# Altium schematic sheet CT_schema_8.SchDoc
size 308 x 210 mm
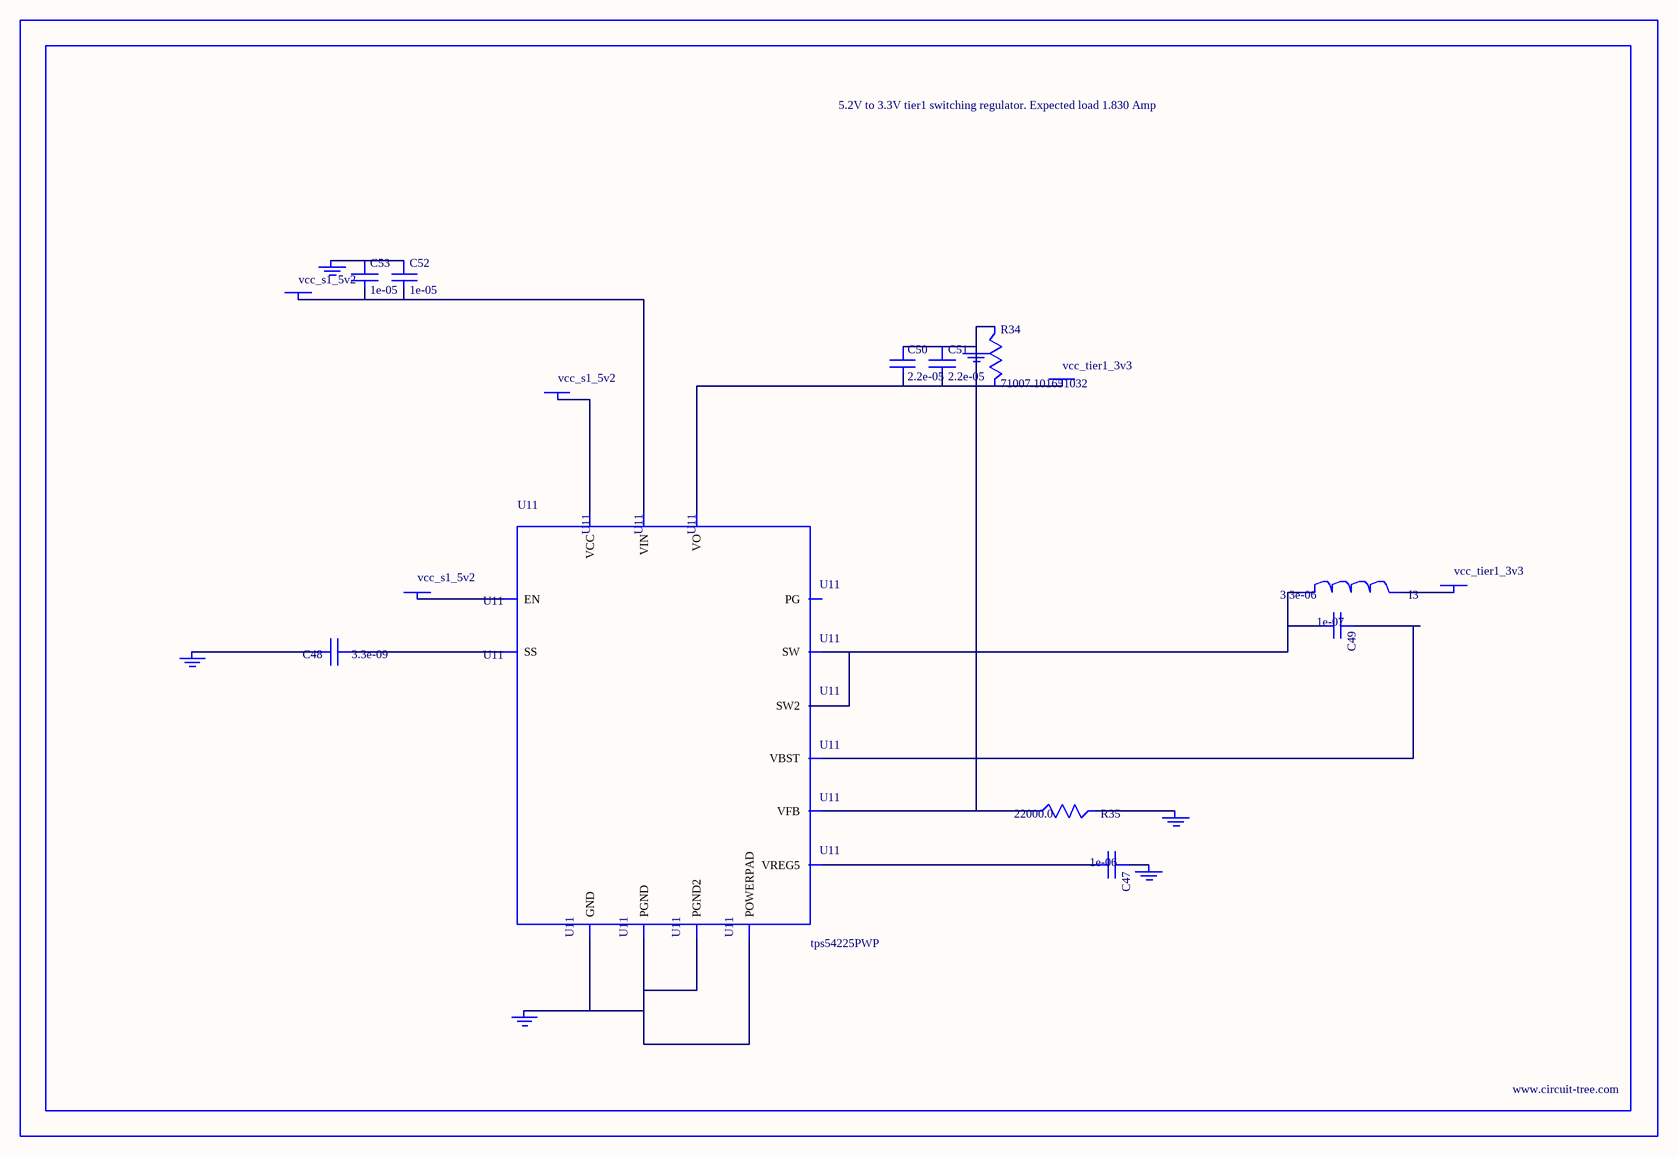
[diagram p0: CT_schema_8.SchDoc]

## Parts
BORDER7  (no value)
C47  1e-06  [C0603]
C48  3.3e-09  [C0402]
C49  1e-07  [C0402]
C50  2.2e-05  [C1210]
C51  2.2e-05  [C1210]
C52  1e-05  [C0805]
C53  1e-05  [C0805]
GND_INSTANCE_7_0  (no value)
GND_INSTANCE_7_1  (no value)
GND_INSTANCE_7_2  (no value)
GND_INSTANCE_7_3  (no value)
GND_INSTANCE_7_4  (no value)
GND_INSTANCE_7_5  (no value)
I3  3.3e-06  [WE-HCI_7030/7040/7050]
POWER_INSTANCE_7_0  vcc_tier1_3v3
POWER_INSTANCE_7_1  vcc_s1_5v2
POWER_INSTANCE_7_2  vcc_tier1_3v3
POWER_INSTANCE_7_3  vcc_s1_5v2
POWER_INSTANCE_7_4  vcc_s1_5v2
R34  71007.101651032  [R0603]
R35  22000.0  [R0603]
U11  tps54225PWP  [HTSSOP14]

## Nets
NetC47_1: C47.1 GND_INSTANCE_7_2.0(GND)
NetC47_2: C47.2 U11.3(VREG5)
NetC48_1: C48.1 U11.4(SS)
NetC48_2: C48.2 GND_INSTANCE_7_3.0(GND)
NetC49_1: C49.1 U11.12(VBST)
NetC49_2: C49.2 I3.1 U11.10(SW) U11.11(SW2)
NetC50_1: C50.1 C51.1 GND_INSTANCE_7_0.0(GND) R34.1 R35.1 U11.2(VFB)
NetC50_2: C50.2 C51.2 POWER_INSTANCE_7_0.0(PWR) R34.2 U11.1(VO)
NetC52_1: C52.1 C53.1 GND_INSTANCE_7_5.0(GND)
NetC52_2: C52.2 C53.2 POWER_INSTANCE_7_3.0(PWR) U11.13(VIN)
NetGND_INSTANCE_7_1_0: GND_INSTANCE_7_1.0(GND) R35.2
NetGND_INSTANCE_7_4_0: GND_INSTANCE_7_4.0(GND) U11.5(GND) U11.8(PGND) U11.9(PGND2) U11.15(POWERPAD)
NetI3_2: I3.2 POWER_INSTANCE_7_2.0(PWR)
NetPOWER_INSTANCE_7_1_0: POWER_INSTANCE_7_1.0(PWR) U11.7(EN)
NetPOWER_INSTANCE_7_4_0: POWER_INSTANCE_7_4.0(PWR) U11.14(VCC)

Not connected (* = marked no-connect by the designer): U11 6(PG)

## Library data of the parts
BORDER7 = BORDER_PAGE7
C47 = C0603C105K3RACTU
C48 = C0402C332K3RAC
C49 = C0402C104K3RACTU
C50 C51 = GRM32ER61E226ME15L
C52 C53 = C0805C106K8RACTU
GND_INSTANCE_7_0-GND_INSTANCE_7_5 = GND
I3 = 744314330
POWER_INSTANCE_7_0-POWER_INSTANCE_7_4 = PWR
R34 = R34
R35 = RC0603JR-0722KL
